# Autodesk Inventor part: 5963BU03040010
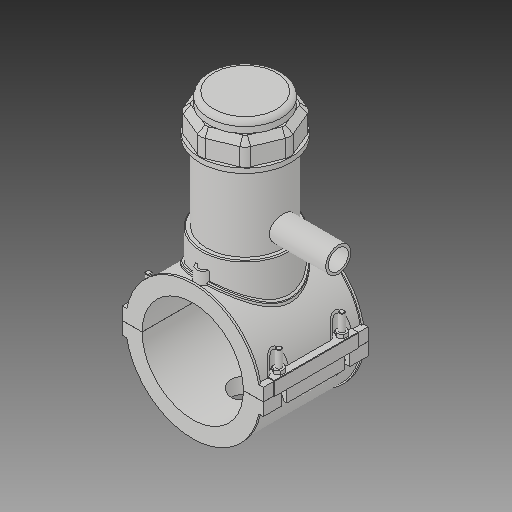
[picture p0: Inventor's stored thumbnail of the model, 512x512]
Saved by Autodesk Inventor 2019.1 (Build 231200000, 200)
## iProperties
Created: 2017-07
Part Number: 5963BU03040010
Material: Generic
Description: PLASSON TAPPING SADDLE 4''IPS x 1''CTS
Document SubType Name: Modeling
Designer: KIM
Mass: 1712.7 g
Surface Area: 2671.49 cm^2
Volume: 1712.7 cm^3
Density: 1 g/cm^3
Appearance: Default
Author: KIM
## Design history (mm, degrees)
derived "5963B.ipt"
feature "Solid1::5963B.ipt"
feature "Solid2::5963B.ipt"
feature "Solid4::5963B.ipt"
feature "Solid5::5963B.ipt"
tag "TaggingFeature1"
body "Solid1"
body "Solid2"
other parameters: "d0" = 114.1, "d2" = 159.004, "d3" = 28.525, "d4" = 118.11, "d5" = 0, "d6" = 0.1, "d8" = 0, "d19" = 6, "d20" = 6, "d21" = 70.866, "d23" = 0, "d24" = 35.433, "d26" = 0, "d29" = 3, "d30" = 38.03333, "d31" = 6, "d32" = 0, "d33" = 0, "d34" = 0.6, "d40" = 77.1316, "d41" = 102.69, "d43" = 0, "d45" = 0, "d47" = 145.031, "d70" = 15, "d72" = 0, "d73" = 6, "d75" = 5, "d76" = 0, "d77" = 5.705, "d78" = 87.05, "d79" = 15, "d80" = 47.244, "d82" = 5 deg, "d84" = 4, "d85" = 14, "d86" = 0, "d87" = 3, "d88" = 0, "d89" = 1, "d90" = 1, "d91" = 94.488, "d92" = 0, "d93" = 0.5, "d94" = 60.05263, "d96" = 151.2966, "d97" = 2.3622, "d98" = 0, "d102" = 1.141, "d120" = 140 deg, "d121" = 24.228, "d122" = 20 deg, "d123" = 296.66, "d124" = 88.998, "d126" = 0, "d143" = 117.523, "d145" = 26.33077, "d149" = 1.7115, "d150" = 28.96385, "d153" = 118.11, "d154" = 0, "d156" = 74.165, "d157" = 160 deg, "d159" = 6.846, "d161" = 1.7115, "d162" = 70.866, "d163" = 0, "d164" = 57.05, "d167" = 11.41, "d168" = 72.3561, "d170" = 3.2805, "d172" = 0, "d173" = 1, "d175" = 57.05, "d176" = 20 deg, "d177" = 7.987, "d178" = 34.23, "d180" = 0, "d183" = 13.692, "d184" = 6.3896, "d185" = 38.38575, "d186" = 38.38575, "d187" = 74.165, "d188" = 10.269, "d189" = 7.987, "d190" = 0, "d191" = 111.2475, "d193" = 6.1236, "d194" = 4.13385, "d195" = 90 deg, "d197" = 0, "d199" = 0, "d200" = 17.115, "d202" = 0, "d203" = 177.038, "d204" = 97.5555, "d205" = 71.883, "d206" = 87.2865, "d207" = 132.7785, "d208" = 138.08964, "d209" = 164.64534, "d210" = 88.3134, "d211" = 102.69, "d212" = 82.152, "d213" = 45.7191, "d216" = 0, "d217" = 11.41, "d218" = 5.705, "d219" = 1.141, "d222" = 114.1, "d224" = 0, "d230" = 6.846, "d233" = 6, "d236" = 79.502, "d237" = 35.433, "d238" = 6.02433, "d240" = 35.433, "d241" = 35.433, "d242" = 35.433, "d243" = 6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
